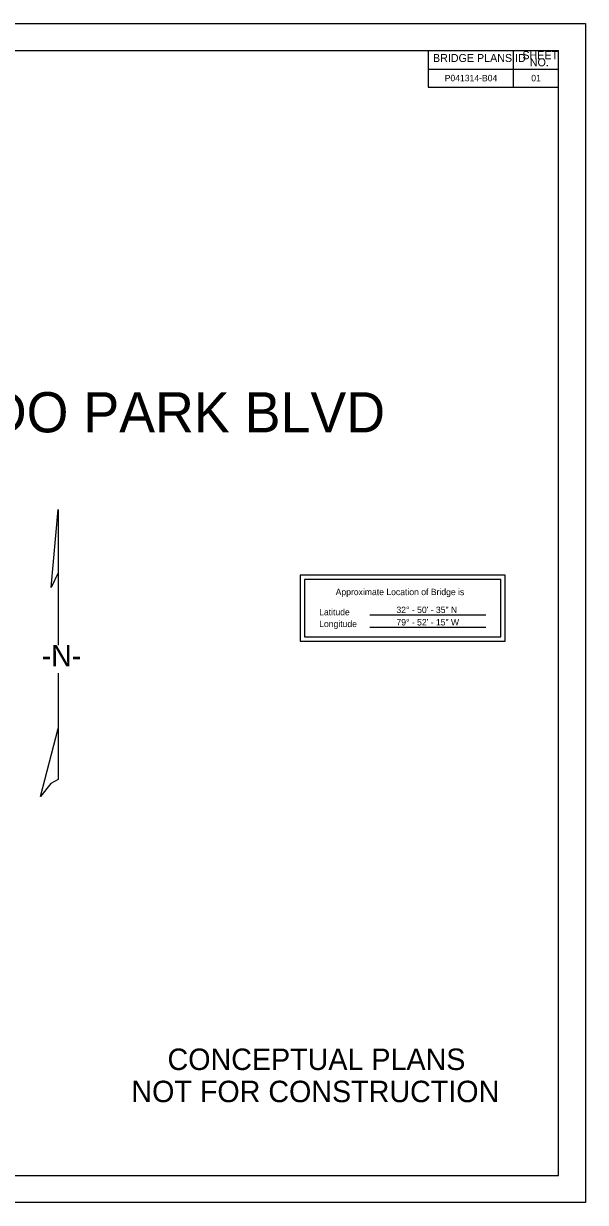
# Model space of a CAD drawing. Extents: x 291 to 2091, y 224 to 1324.
# Drawn here: x 1567 to 2091, y 224 to 1324 of the extents above; entities that cross this region are included whole.
import ezdxf

# ---------------------------------------------------------------- set-up
doc = ezdxf.new("R2010")
doc.units = 0
for name, color, linetype in [('BR_BORDER LINES', 7, 'Continuous'), ('BR_TEXT', 7, 'Continuous'), ('Default', 7, 'Continuous'), ('GN_TitleSheetMap', 7, 'Continuous'), ('RD_SHT_IplotShp', 7, 'Continuous')]:
    doc.layers.add(name, color=color, linetype=linetype)

msp = doc.modelspace()

# ---------------------------------------------------------------- linework, layer by layer
at = {"layer": 'BR_BORDER LINES'}
for p, q in [((391.1, 1299), (2066.1, 1299)), ((1944.4, 1299), (1944.4, 1264.8)), ((2023.9, 1264.8), (2023.9, 1299)), ((2066.1, 249.1), (2066.1, 1299)), ((1944.4, 1281.5), (2066.1, 1281.5)), ((2066.1, 1240.8), (2066.1, 1265.7)), ((1944.4, 1264.8), (2066.1, 1264.8)), ((2066.1, 888.4), (2066.1, 1240.8)), ((391.1, 249.1), (2066.1, 249.1))]:
    msp.add_line(p, q, dxfattribs=at)
at = {"layer": 'BR_TEXT'}
for points in [[(2016.1, 809.3), (1825, 809.3), (1825, 747.7), (2016.1, 747.7)], [(2012.1, 805.3), (1829, 805.3), (1829, 751.7), (2012.1, 751.7)]]:
    msp.add_lwpolyline(points, close=True, dxfattribs=at)
at = {"layer": 'Default'}
for p, q in [((1592.6, 797.9), (1599.3, 870.7)), ((1599.3, 870.7), (1599.3, 811.4)), ((1599.3, 811.4), (1592.6, 797.9)), ((1599.3, 811.4), (1599.3, 770.3)), ((1599.3, 770.3), (1599.3, 744.1)), ((1599.3, 718), (1599.3, 666.2)), ((1582.8, 602.7), (1599.3, 666.2)), ((1599.3, 666.2), (1599.3, 658.3)), ((1599.3, 658.3), (1599.3, 618.6))]:
    msp.add_line(p, q, dxfattribs=at)
msp.add_lwpolyline([(1599.3, 618.6), (1592.2, 614.8), (1582.8, 602.7)], dxfattribs=at)
at = {"layer": 'GN_TitleSheetMap'}
for p, q in [((1890, 772.3), (1998.1, 772.3)), ((1890, 760.7), (1998.1, 760.7))]:
    msp.add_line(p, q, dxfattribs=at)
at = {"layer": 'RD_SHT_IplotShp'}
msp.add_lwpolyline([(291.1, 1324), (2091.1, 1324), (2091.1, 224), (291.1, 224)], close=True, dxfattribs=at)

# ---------------------------------------------------------------- texts
at = {"layer": 'BR_TEXT'}
for s, height, p in [('SHEET', 7.47, (2032.3, 1290.8)), ('BRIDGE PLANS ID', 7.466, (1948.9, 1288.2)), ('NO.', 7.47, (2039.2, 1284.2)), ('CONSTRUCT BRIDGE OVER WANDO PARK BLVD', 37.5, (725.6, 942.6)), ('Approximate Location of Bridge is', 6, (1858.1, 790.7)), ('Latitude', 6, (1842.7, 771.9)), ('32%%D - 50\' - 35" N', 6, (1914.8, 774)), ('Longitude', 6, (1842.7, 760.9)), ('79%%D - 52\' - 15" W', 6, (1914.8, 762.4)), ('CONCEPTUAL PLANS', 20, (1701.2, 347.6)), ('NOT FOR CONSTRUCTION', 20, (1667.5, 317.6))]:
    msp.add_text(s, height=height, dxfattribs=at).set_placement(p)
for s, height, p in [('P041314-B04', 5.999, (1959.8, 1270.2)), ('01', 6, (2040.6, 1270.2))]:
    msp.add_text(s, height=height, rotation=0.0002, dxfattribs=at).set_placement(p)
at = {"layer": 'Default'}
msp.add_text('-N-', height=20, dxfattribs=at).set_placement((1583.7, 724.3))

doc.saveas('drawing.dxf')
